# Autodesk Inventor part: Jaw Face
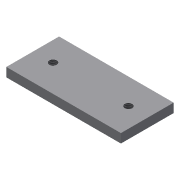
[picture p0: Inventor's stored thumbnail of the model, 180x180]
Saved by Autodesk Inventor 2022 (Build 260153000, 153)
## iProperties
Created: 2002-02
Part Number: Jaw Face
Document SubType Name: Modeling
Designer: ***
Density: 1 g/cm^3
Material: Generic
Mass: 15.6207 g
Surface Area: 67.651 cm^2
Volume: 15.6207 cm^3
Appearance: Default
Control State: 0
Master: False
Checked Out: False
Shininess: 77.0
Length Units: 11269
Angle Units: 11279
Time Units: 11290
Mass Units: 11283
Length Display Precision: 3
Angle Display Precision: 2
Compacted: True
Density: 0.0
Volumn: 0.0
Area: 0.0
PropertySet Name: Model Information
Author: ***
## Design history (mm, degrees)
sketch "Sketch1"
  geometry: L1 (-79.661, -8.43)-(-3.661, -8.43); L2 (-3.661, -8.43)-(-3.661, -43.43); L3 (-3.661, -43.43)-(-79.661, -43.43); L4 (-79.661, -43.43)-(-79.661, -8.43)
  constraints: 8 end point, 2 parallel, 1 horizontal, 1 perpendicular
  dimensions: "d0" = 76 distance of L2.end L3.end; "d3" = 35 distance of L1.end L2.end
extrude "Extrusion1" new body sketch "Sketch1" stored distance "d7" = 6; taper "d8" = 0 deg
hole "Hole1" diameter "d11" = 4.917; stored, may be unused: countersink angle "d15" = 90 deg, drill point angle "d17" = 118 deg; dims "d9" = 13, "d10" = 18, "d12" = 12, "d13" = 4, "d14" = 2, "d16" = 17.1
pattern_linear "Rectangular Pattern1" dims "d20" = -50
body "Solid1"
